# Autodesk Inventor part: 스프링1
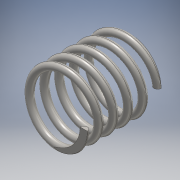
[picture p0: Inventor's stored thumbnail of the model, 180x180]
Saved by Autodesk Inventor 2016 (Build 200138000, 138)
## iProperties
Created: 2019-11
Part Number: 스프링1
Material: 스테인레스 스틸
Document SubType Name: Modeling
Designer: user
Density: 8 g/cm^3
Appearance: 반연마
Mass: 6.57605 g
Surface Area: 16.7268 cm^2
Volume: 0.822006 cm^3
Author: user
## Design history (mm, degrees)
sketch "스케치1"
  geometry: L1 (0, 0)-(8.5, 0); L2 (8.5, 0)-(8.5, 20.5); L3 (8.5, 20.5)-(0, 20.5); L4 (0, 20.5)-(0, 0); C1 r 1 at (8.5, 0)
  constraints: 8 end point, 2 parallel, 1 centre point, 1 coincident, 1 horizontal, 1 perpendicular
  dimensions: "d0" = 17 diameter of L2 L4; "d1" = 2 diameter of C1; "d2" = 20.5 distance of L1.end L2.end (derived)
feature "코일1" sketch "스케치1" pitch "d3" = 10; turns "d5" = 5; dims "d4" = 20.5 (= d2), "d6" = 0, angle "d7" = 90 deg, angle "d8" = 90 deg, "d9" = 0, "d10" = 0
sketch "스케치2"
  geometry: L1 (-15.597, 20.5)-(15.597, 20.5); L2 (15.597, 20.5)-(15.597, 0); L3 (15.597, 0)-(-15.597, 0); L4 (-15.597, 0)-(-15.597, 20.5); 2 further points
  constraints: 8 end point, 2 parallel, 1 coincident, 1 horizontal, 1 midpoint, 1 perpendicular
  dimensions: "d11" = 20.5 distance of L1.end L2.end (= d2)
extrude "돌출1" sketch "스케치2" stored distance "d12" = 50; taper "d13" = 0 deg
node "솔리드1"
